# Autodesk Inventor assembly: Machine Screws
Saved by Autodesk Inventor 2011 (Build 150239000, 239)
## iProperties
Created: 2008-03
Part Number: Machine Screws
Document SubType Name: Assembly
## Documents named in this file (2)
- C:\Data Folder\VEX 2011\Inventor Datasets\Unit 7\Components\Machine Screws.iam
- C:\Data Folder\VEX 2011\Inventor Datasets\Unit 7\Components\ANSI B18.6.3 - 1-64 UNC - 0.125(9).ipt
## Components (8 placed, 1 different names)
1. Cross Recessed Fillister Head Machine Screw - Type IA - Inch 1 - 64 - 1/8:1
2. Cross Recessed Fillister Head Machine Screw - Type IA - Inch 1 - 64 - 1/8:2
3. Cross Recessed Fillister Head Machine Screw - Type IA - Inch 1 - 64 - 1/8:3
4. Cross Recessed Fillister Head Machine Screw - Type IA - Inch 1 - 64 - 1/8:4
5. Cross Recessed Fillister Head Machine Screw - Type IA - Inch 1 - 64 - 1/8:5
6. Cross Recessed Fillister Head Machine Screw - Type IA - Inch 1 - 64 - 1/8:6
7. Cross Recessed Fillister Head Machine Screw - Type IA - Inch 1 - 64 - 1/8:7
8. Cross Recessed Fillister Head Machine Screw - Type IA - Inch 1 - 64 - 1/8:8
